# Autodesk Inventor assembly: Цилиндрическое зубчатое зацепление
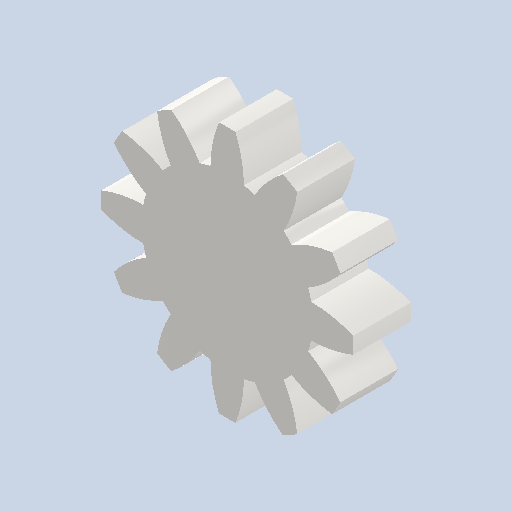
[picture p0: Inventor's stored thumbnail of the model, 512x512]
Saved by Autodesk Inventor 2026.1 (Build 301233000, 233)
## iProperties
ClientObjectVersion: 1
Created: 2026-01
Part Number: Цилиндрическое зубчатое зацепление
Document SubType Name: Assembly
Designer: Yury Melnikov
Categories: <?xml version="1.0" encoding="UTF-16"?> <MemberInstance><Categories><FamilyTemplate/><ParamToTemplateMap><ParamToTemplate><ParamToTemplate CategoryParameter="//
Author: Yury Melnikov
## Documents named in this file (2)
- C:\Users\user\Documents\Проекты\ВсОШ_РОБО\Робот V2\Шестерни ось Z\Мастер проектирования\Цилиндрическое зубчатое зацепление1.iam
- C:\Users\user\Documents\Проекты\ВсОШ_РОБО\Робот V2\Шестерни ось Z\Мастер проектирования\Цилиндрическое зубчатое зацепление11.ipt
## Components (1 placed, 1 different names)
1. Цилиндрическое зубчатое зацепление1:1
